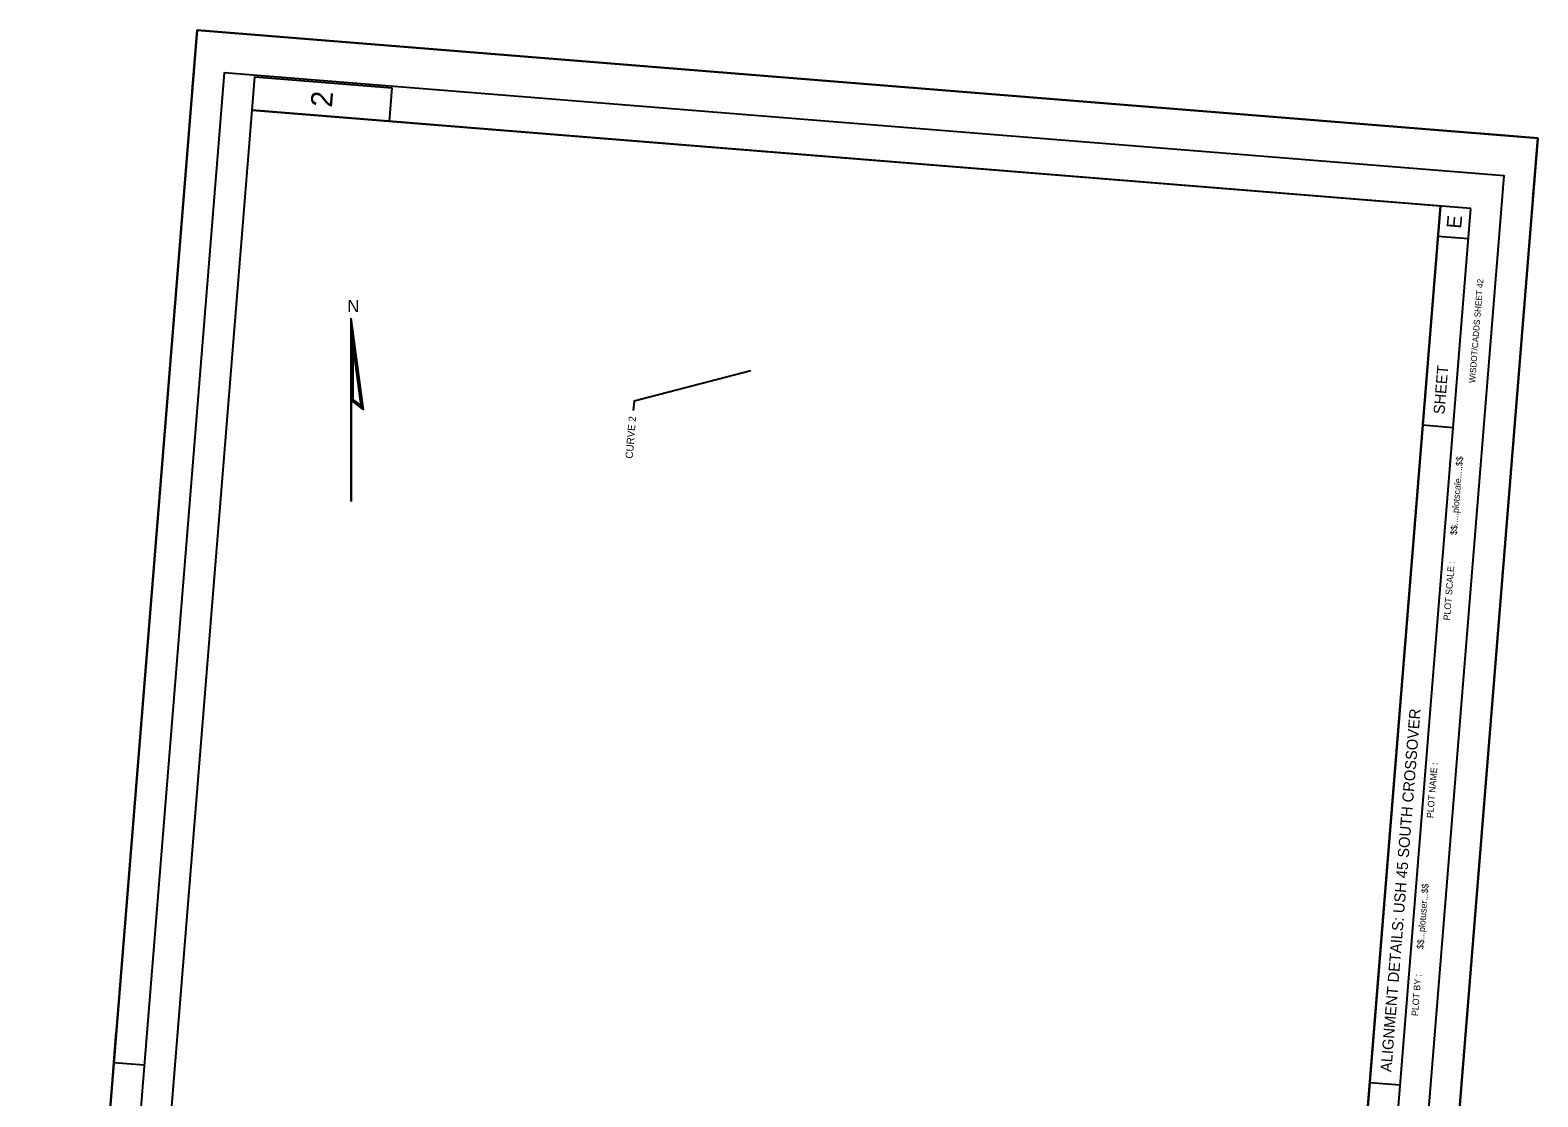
# Model space of a CAD drawing. Extents: x 359466 to 360699, y 172691 to 174474.
# Drawn here: x 359466 to 360699, y 173601 to 174474 of the extents above; entities that cross this region are included whole.
import ezdxf

# ---------------------------------------------------------------- set-up
doc = ezdxf.new("R2010")
doc.units = 0
for name, color, linetype in [('P_MISC', 7, 'Continuous'), ('P_MISC_NoPlot', 7, 'Continuous'), ('P_MISC_TXT', 7, 'Continuous'), ('P_RDWY_Text', 7, 'Continuous'), ('PLT_Sheet_Border', 7, 'Continuous'), ('PLT_Sheet_Info', 7, 'Continuous')]:
    doc.layers.add(name, color=color, linetype=linetype)

msp = doc.modelspace()

# ---------------------------------------------------------------- linework, layer by layer
at = {"layer": 'P_MISC'}
for p, q in [((359738.1, 174163.7), (359728.1, 174238.7)), ((359728.1, 174171.2), (359728.1, 174238.7)), ((359728.9, 174171.5), (359728.9, 174227.4)), ((359737.1, 174165.3), (359728.9, 174227.4)), ((359729.6, 174171.9), (359729.6, 174216.1)), ((359736.2, 174167), (359729.6, 174216.1)), ((359729.6, 174171.9), (359736.2, 174167)), ((359728.1, 174171.2), (359738.1, 174163.7)), ((359728.1, 174088.7), (359728.1, 174171.2)), ((359728.4, 174088.7), (359728.4, 174171)), ((359728.9, 174171.5), (359737.1, 174165.3))]:
    msp.add_line(p, q, dxfattribs=at)
msp.add_lwpolyline([(359728.1, 174238.6), (359728.1, 174238.6)], dxfattribs=at)
at = {"layer": 'P_MISC_NoPlot'}
msp.add_lwpolyline([(359520.5, 172838.9), (359647, 174408.8), (360618.8, 174330.5), (360492.3, 172760.6)], close=True, dxfattribs=at)
at = {"layer": 'P_MISC_TXT'}
msp.add_lwpolyline([(360054.9, 174195.5), (359959.4, 174170.6), (359958.8, 174163)], dxfattribs=at)
at = {"layer": 'P_RDWY_Text'}
msp.add_lwpolyline([(359465.5, 172779.8), (359602.1, 174474.3), (360698.5, 174386), (360562, 172691.5)], close=True, dxfattribs=at)
at = {"layer": 'PLT_Sheet_Border'}
for points in [[(360562, 172691.5), (360698.5, 174386), (359602.1, 174474.3), (359465.5, 172779.8)], [(360538, 172705.5), (360670.9, 174355.1), (359624.3, 174439.4), (359491.4, 172789.8)]]:
    msp.add_lwpolyline(points, close=True, dxfattribs=at)
at = {"layer": 'PLT_Sheet_Info'}
for p, q in [((359598.1, 174424.5), (359602.1, 174474.3)), ((359651.9, 174470.3), (359602.1, 174474.3)), ((359520.5, 172838.9), (359647, 174408.8)), ((360643.7, 174328.5), (359647, 174408.8)), ((360698.5, 174386), (360648.7, 174390)), ((360694.5, 174336.2), (360698.5, 174386)), ((360492.3, 172760.6), (360618.8, 174330.5)), ((360517.2, 172758.5), (360643.7, 174328.5)), ((360641.7, 174303.5), (360616.8, 174305.5)), ((360629.3, 174149), (360604.3, 174151)), ((359532, 173604.7), (359536, 173654.5)), ((359534, 173629.6), (359558.9, 173627.6)), ((360585.9, 173610.8), (360561, 173612.8))]:
    msp.add_line(p, q, dxfattribs=at)
msp.add_lwpolyline([(359647, 174408.8), (359649.2, 174436.2), (359761.3, 174427.2), (359759.1, 174399.7)], close=True, dxfattribs=at)

# ---------------------------------------------------------------- texts
at = {"layer": 'P_MISC'}
msp.add_text('N', height=10, dxfattribs=at).set_placement((359725, 174243.6))
at = {"layer": 'P_MISC_TXT'}
msp.add_text('CURVE 2', height=6, rotation=85.3932, dxfattribs=at).set_placement((359958.3, 174123.5))
at = {"layer": 'PLT_Sheet_Info'}
for s, height, p in [('2', 17.5, (359712.3, 174410.7)), ('E', 12, (360635.8, 174311.6)), ('WISDOT/CADDS SHEET 42', 5, (360647.2, 174185.4)), ('SHEET ', 9, (360622.1, 174159.7)), ('$$.....plotscale.....$$', 5.4, (360632.2, 174061)), ('PLOT SCALE : ', 5.4, (360626.6, 173991.1)), ('ALIGNMENT DETAILS: USH 45 SOUTH CROSSOVER         ', 9, (360578.7, 173621.4)), ('PLOT NAME :                      ', 5.4, (360613, 173829.3)), ('$$...plotuser...$$', 5.4, (360604.9, 173722.1)), ('PLOT BY :', 5.4, (360600.5, 173667.3))]:
    msp.add_text(s, height=height, rotation=85.3932, dxfattribs=at).set_placement(p)

doc.saveas('drawing.dxf')
